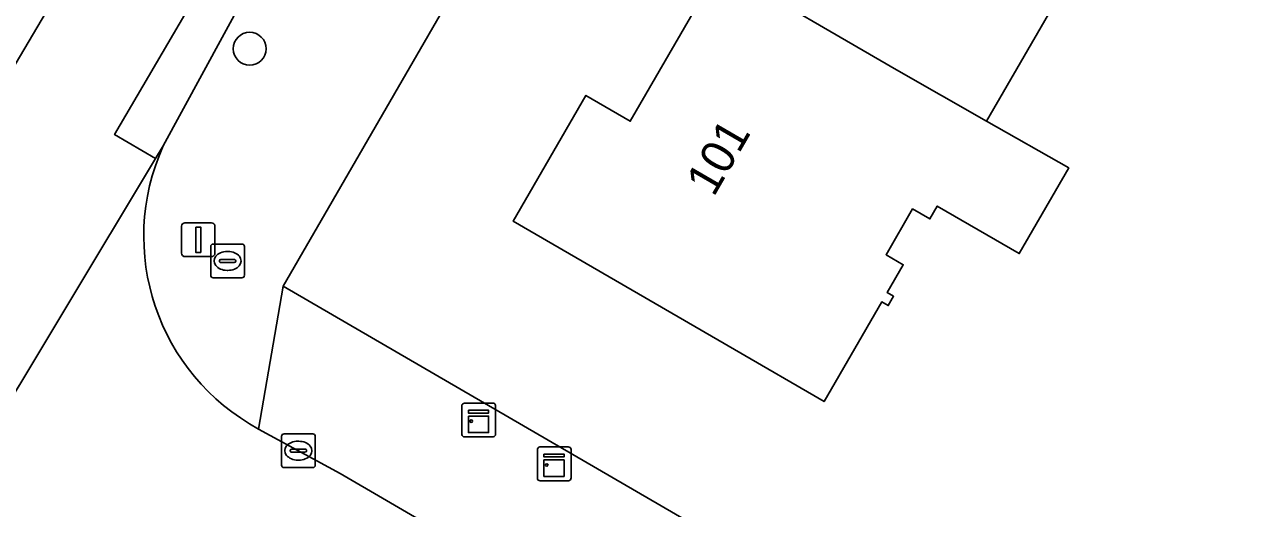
# Model space of a CAD drawing. Extents: x 160349 to 161355, y 381727 to 382854.
# Drawn here: x 160778.71 to 160815.25, y 382169.55 to 382183.88 of the extents above; entities that cross this region are included whole.
import ezdxf

# ---------------------------------------------------------------- set-up
doc = ezdxf.new("R2010")
doc.units = 0
for name, color, linetype in [('IMGEO_Boom', 7, 'Continuous'), ('IMGEO_Brandkraan', 7, 'Continuous'), ('IMGEO_Erf', 7, 'Continuous'), ('IMGEO_Kast', 7, 'Continuous'), ('IMGEO_Kolk', 7, 'Continuous'), ('IMGEO_Lichtmast', 7, 'Continuous'), ('IMGEO_Pand', 7, 'Continuous'), ('IMGEO_Pand_nummerreeks', 7, 'Continuous'), ('IMGEO_Rijbaan_lokaal_gesloten', 7, 'Continuous'), ('IMGEO_Rijbaan_lokaal_open', 7, 'Continuous'), ('IMGEO_Voetpad_open', 7, 'Continuous')]:
    doc.layers.add(name, color=color, linetype=linetype)

msp = doc.modelspace()

# ---------------------------------------------------------------- linework, layer by layer
at = {"layer": 'IMGEO_Boom'}
msp.add_circle((160785.384, 382183.165), 0.489, dxfattribs=at)
at = {"layer": 'IMGEO_Brandkraan'}
for p, q in [((160784.302, 382177.377), (160785.154, 382177.377)), ((160784.227, 382176.451), (160784.227, 382177.303)), ((160784.715, 382177.157), (160784.74, 382177.157)), ((160785.228, 382177.303), (160785.228, 382176.451)), ((160784.486, 382176.871), (160784.486, 382176.883)), ((160784.924, 382176.834), (160784.526, 382176.834)), ((160784.529, 382176.92), (160784.927, 382176.92)), ((160784.97, 382176.883), (160784.97, 382176.871)), ((160785.154, 382176.377), (160784.302, 382176.377)), ((160784.738, 382176.597), (160784.713, 382176.597))]:
    msp.add_line(p, q, dxfattribs=at)
for points in [[(160784.302, 382177.377), (160785.154, 382177.377)], [(160784.227, 382176.451), (160784.227, 382177.303)], [(160785.228, 382177.303), (160785.228, 382176.451)], [(160785.154, 382176.377), (160784.302, 382176.377)]]:
    msp.add_lwpolyline(points, dxfattribs=at)
for centre, radius, start, end in [((160784.304, 382177.301), 0.0765, 91.552, 178.448), ((160784.304, 382177.301), 0.0765, 91.552, 178.448), ((160785.152, 382177.301), 0.0765, 1.552, 88.448), ((160785.152, 382177.301), 0.0765, 1.552, 88.448), ((160784.526, 382176.88), 0.0403, 85.8775, 175.7526), ((160784.523, 382176.87), 0.0366, 178.938, 274.7102), ((160784.927, 382176.877), 0.043, 264.8664, 352.4533), ((160784.931, 382176.882), 0.0386, 1.7309, 96.639), ((160784.304, 382176.453), 0.0765, 181.552, 268.448), ((160784.304, 382176.453), 0.0765, 181.552, 268.448), ((160785.152, 382176.453), 0.0765, 271.552, 358.448), ((160785.152, 382176.453), 0.0765, 271.552, 358.448)]:
    msp.add_arc(centre, radius, start, end, dxfattribs=at)
for centre, major_axis, ratio, start_param, end_param in [((160784.714, 382176.877), (-0.387, 0.002), 0.722429, 4.712389, 7.853982), ((160784.739, 382176.877), (-0.39, 0.002), 0.717154, 1.570796, 4.712389)]:
    msp.add_ellipse(centre, major_axis=major_axis, ratio=ratio, start_param=start_param, end_param=end_param, dxfattribs=at)
at = {"layer": 'IMGEO_Erf'}
for points in [[(160933.344, 382182.327), (160924.218, 382191.389), (160906.426, 382206.128), (160902.418, 382205.455), (160886.177, 382214.66), (160875.171, 382221.124), (160873.887, 382226.28), (160832.686, 382250), (160830.042, 382251.522), (160829.161, 382250), (160786.376, 382176.128), (160847.679, 382140.543), (160850.05, 382144.635)], [(160810.592, 382186.807), (160807.24, 382181.022), (160809.683, 382179.634), (160808.214, 382177.097), (160805.782, 382178.505), (160805.561, 382178.124), (160805.05, 382178.419), (160804.263, 382177.06), (160804.773, 382176.764), (160804.296, 382175.941), (160804.486, 382175.83), (160804.325, 382175.553), (160804.134, 382175.663), (160802.425, 382172.712), (160799.769, 382174.25), (160793.201, 382178.055), (160795.36, 382181.78), (160796.673, 382181.019), (160799.321, 382185.589)]]:
    msp.add_lwpolyline(points, dxfattribs=at)
at = {"layer": 'IMGEO_Kast'}
for p, q in [((160791.753, 382172.664), (160792.594, 382172.664)), ((160792.594, 382172.664), (160791.753, 382172.664)), ((160791.678, 382171.739), (160791.678, 382172.58)), ((160791.678, 382172.58), (160791.678, 382171.739)), ((160792.678, 382172.589), (160792.678, 382171.748)), ((160792.678, 382171.748), (160792.678, 382172.589)), ((160792.603, 382171.664), (160791.762, 382171.664)), ((160791.762, 382171.664), (160792.603, 382171.664)), ((160793.917, 382170.44), (160793.917, 382171.281)), ((160793.917, 382171.281), (160793.917, 382170.44)), ((160793.992, 382171.365), (160794.833, 382171.365)), ((160794.833, 382171.365), (160793.992, 382171.365)), ((160794.917, 382171.29), (160794.917, 382170.449)), ((160794.917, 382170.449), (160794.917, 382171.29)), ((160794.842, 382170.365), (160794.001, 382170.365)), ((160794.001, 382170.365), (160794.842, 382170.365))]:
    msp.add_line(p, q, dxfattribs=at)
for points in [[(160791.873, 382172.454), (160792.473, 382172.454), (160792.473, 382172.369), (160791.873, 382172.369), (160791.873, 382172.454)], [(160791.873, 382172.279), (160792.473, 382172.279), (160792.473, 382171.79), (160791.873, 382171.79), (160791.873, 382172.279)], [(160794.112, 382171.155), (160794.712, 382171.155), (160794.712, 382171.07), (160794.112, 382171.07), (160794.112, 382171.155)], [(160794.112, 382170.98), (160794.712, 382170.98), (160794.712, 382170.491), (160794.112, 382170.491), (160794.112, 382170.98)]]:
    msp.add_lwpolyline(points, dxfattribs=at)
for centre in [(160791.957, 382172.128), (160794.196, 382170.829)]:
    msp.add_circle(centre, 0.0377, dxfattribs=at)
for centre, start, end in [((160791.756, 382172.586), 92.4484, 184.2845), ((160791.756, 382172.586), 92.4484, 184.2845), ((160792.6, 382172.586), 2.4484, 94.2845), ((160792.6, 382172.586), 2.4484, 94.2845), ((160791.756, 382171.742), 182.4484, 274.2845), ((160791.756, 382171.742), 182.4484, 274.2845), ((160792.6, 382171.742), 272.4484, 4.2845), ((160792.6, 382171.742), 272.4484, 4.2845), ((160793.995, 382171.287), 92.4484, 184.2845), ((160793.995, 382171.287), 92.4484, 184.2845), ((160794.839, 382171.287), 2.4484, 94.2845), ((160794.839, 382171.287), 2.4484, 94.2845), ((160793.995, 382170.443), 182.4484, 274.2845), ((160793.995, 382170.443), 182.4484, 274.2845), ((160794.839, 382170.443), 272.4484, 4.2845), ((160794.839, 382170.443), 272.4484, 4.2845)]:
    msp.add_arc(centre, 0.0779, start, end, dxfattribs=at)
at = {"layer": 'IMGEO_Kolk'}
for p, q in [((160786.328, 382170.829), (160786.328, 382171.681)), ((160786.403, 382171.755), (160787.255, 382171.755)), ((160786.816, 382171.535), (160786.841, 382171.535)), ((160787.329, 382171.681), (160787.329, 382170.829)), ((160786.587, 382171.249), (160786.587, 382171.261)), ((160787.025, 382171.212), (160786.627, 382171.212)), ((160786.63, 382171.298), (160787.028, 382171.298)), ((160787.071, 382171.261), (160787.071, 382171.249)), ((160786.839, 382170.975), (160786.814, 382170.975)), ((160787.255, 382170.755), (160786.403, 382170.755))]:
    msp.add_line(p, q, dxfattribs=at)
for points in [[(160786.328, 382170.829), (160786.328, 382171.681)], [(160786.403, 382171.755), (160787.255, 382171.755)], [(160787.329, 382171.681), (160787.329, 382170.829)], [(160787.255, 382170.755), (160786.403, 382170.755)]]:
    msp.add_lwpolyline(points, dxfattribs=at)
for centre, radius, start, end in [((160786.405, 382171.679), 0.0765, 91.552, 178.448), ((160786.405, 382171.679), 0.0765, 91.552, 178.448), ((160787.253, 382171.679), 0.0765, 1.552, 88.448), ((160787.253, 382171.679), 0.0765, 1.552, 88.448), ((160786.627, 382171.258), 0.0403, 85.8775, 175.7526), ((160786.624, 382171.248), 0.0366, 178.938, 274.7102), ((160787.028, 382171.255), 0.043, 264.8664, 352.4533), ((160787.032, 382171.26), 0.0386, 1.7309, 96.639), ((160786.405, 382170.831), 0.0765, 181.552, 268.448), ((160786.405, 382170.831), 0.0765, 181.552, 268.448), ((160787.253, 382170.831), 0.0765, 271.552, 358.448), ((160787.253, 382170.831), 0.0765, 271.552, 358.448)]:
    msp.add_arc(centre, radius, start, end, dxfattribs=at)
for centre, major_axis, ratio, start_param, end_param in [((160786.815, 382171.255), (-0.387, 0.002), 0.722429, 4.712389, 7.853982), ((160786.84, 382171.255), (-0.39, 0.002), 0.717154, 1.570796, 4.712389)]:
    msp.add_ellipse(centre, major_axis=major_axis, ratio=ratio, start_param=start_param, end_param=end_param, dxfattribs=at)
at = {"layer": 'IMGEO_Lichtmast'}
for p, q in [((160783.365, 382177.105), (160783.365, 382177.905)), ((160783.365, 382177.905), (160783.365, 382177.105)), ((160783.465, 382178.005), (160784.255, 382178.005)), ((160784.255, 382178.005), (160783.465, 382178.005)), ((160784.355, 382177.905), (160784.355, 382177.105)), ((160784.355, 382177.105), (160784.355, 382177.905)), ((160784.255, 382177.005), (160783.465, 382177.005)), ((160783.465, 382177.005), (160784.255, 382177.005))]:
    msp.add_line(p, q, dxfattribs=at)
msp.add_lwpolyline([(160783.785, 382177.88), (160783.935, 382177.88), (160783.935, 382177.13), (160783.785, 382177.13), (160783.785, 382177.88)], dxfattribs=at)
for centre, start, end in [((160783.465, 382177.905), 90, 180), ((160783.465, 382177.905), 90, 180), ((160784.255, 382177.905), 0, 90), ((160784.255, 382177.905), 360, 90), ((160783.465, 382177.105), 180, 270), ((160783.465, 382177.105), 180, 270), ((160784.255, 382177.105), 270, 0), ((160784.255, 382177.105), 270, 0)]:
    msp.add_arc(centre, 0.1, start, end, dxfattribs=at)
at = {"layer": 'IMGEO_Pand'}
for points in [[(160807.24, 382181.022), (160810.592, 382186.807), (160813.31, 382185.219), (160814.665, 382187.559), (160809.301, 382190.706), (160804.051, 382193.749), (160799.321, 382185.589), (160804.574, 382182.544)], [(160807.24, 382181.022), (160804.574, 382182.544), (160799.321, 382185.589), (160796.673, 382181.019), (160795.36, 382181.78), (160793.201, 382178.055), (160799.769, 382174.25), (160802.425, 382172.712), (160804.134, 382175.663), (160804.325, 382175.553), (160804.486, 382175.83), (160804.296, 382175.941), (160804.773, 382176.764), (160804.263, 382177.06), (160805.05, 382178.419), (160805.561, 382178.124), (160805.782, 382178.505), (160808.214, 382177.097), (160809.683, 382179.634)]]:
    msp.add_lwpolyline(points, close=True, dxfattribs=at)
at = {"layer": 'IMGEO_Rijbaan_lokaal_gesloten'}
for points in [[(160812.989, 382240.37), (160784.239, 382192.537), (160777.906, 382181.828), (160776.425, 382182.776), (160776.168, 382182.334), (160769.164, 382170.249), (160770.494, 382169.628), (160766.428, 382162.546), (160760.731, 382152.677), (160755.42, 382142.776), (160751.633, 382135.727), (160748.813, 382130.153), (160747.076, 382126.71), (160742.756, 382117.768), (160731.871, 382093.997), (160727.444, 382083.882), (160724.887, 382077.653), (160720.494, 382066.374), (160710.123, 382039.204), (160704.275, 382025.25)], [(160798.28, 382218.963), (160786.323, 382199.028), (160781.786, 382191.466), (160779.334, 382187.527), (160778.121, 382185.508), (160776.823, 382183.463), (160776.425, 382182.776), (160777.906, 382181.828), (160784.239, 382192.537), (160812.989, 382240.37)], [(160805.748, 382221.628), (160792.985, 382200.423), (160781.379, 382180.62), (160782.592, 382179.909), (160782.82, 382180.287), (160785.167, 382184.605), (160787.293, 382188.166), (160791.017, 382194.317), (160795.414, 382201.651), (160798.503, 382206.859), (160798.962, 382207.633)], [(160696.524, 381990.659), (160696.749, 381990.258), (160698.267, 381993.805), (160702.724, 382005.472), (160701.297, 382006.186), (160706.444, 382018.907), (160712.871, 382036.35), (160718.969, 382052.415), (160728.018, 382076.284), (160733.461, 382089.005), (160737.526, 382098.251), (160743.231, 382110.677), (160748.477, 382121.661), (160754.903, 382134.448), (160758.33, 382141.071), (160759.953, 382144.071), (160767.084, 382156.956), (160773.018, 382167.169), (160774.485, 382166.436), (160782.592, 382179.909), (160781.379, 382180.62), (160792.985, 382200.423)]]:
    msp.add_lwpolyline(points, dxfattribs=at)
at = {"layer": 'IMGEO_Rijbaan_lokaal_open'}
for points in [[(160782.82, 382180.287), (160782.592, 382179.909), (160774.485, 382166.436)], [(160788.073, 382170.575), (160785.65, 382171.897)], [(160783.128, 382167.779), (160828.147, 382141.575), (160830.614, 382145.814), (160814.009, 382155.479), (160810.768, 382157.365), (160788.073, 382170.575)]]:
    msp.add_lwpolyline(points, dxfattribs=at)
msp.add_arc((160788.736, 382177.61), 6.493, 155.652, 241.6272, dxfattribs=at)
at = {"layer": 'IMGEO_Voetpad_open'}
for points in [[(160785.65, 382171.897), (160786.376, 382176.128), (160829.161, 382250)], [(160787.293, 382188.166), (160785.167, 382184.605), (160782.82, 382180.287)]]:
    msp.add_lwpolyline(points, dxfattribs=at)
msp.add_lwpolyline([(160786.376, 382176.128), (160785.65, 382171.897), (160788.073, 382170.575), (160810.768, 382157.365), (160810.994, 382157.755), (160814.235, 382155.868), (160814.009, 382155.479), (160830.614, 382145.814), (160832.472, 382144.733), (160833.478, 382146.461), (160836.59, 382144.65), (160835.584, 382142.922), (160844.183, 382137.917), (160847.679, 382140.543)], close=True, dxfattribs=at)
msp.add_arc((160788.736, 382177.61), 6.493, 155.652, 241.6272, dxfattribs=at)

# ---------------------------------------------------------------- texts
at = {"layer": 'IMGEO_Pand_nummerreeks'}
msp.add_text('101', height=1, rotation=59.9063, dxfattribs=at).set_placement((160799.148, 382178.748))

doc.saveas('drawing.dxf')
